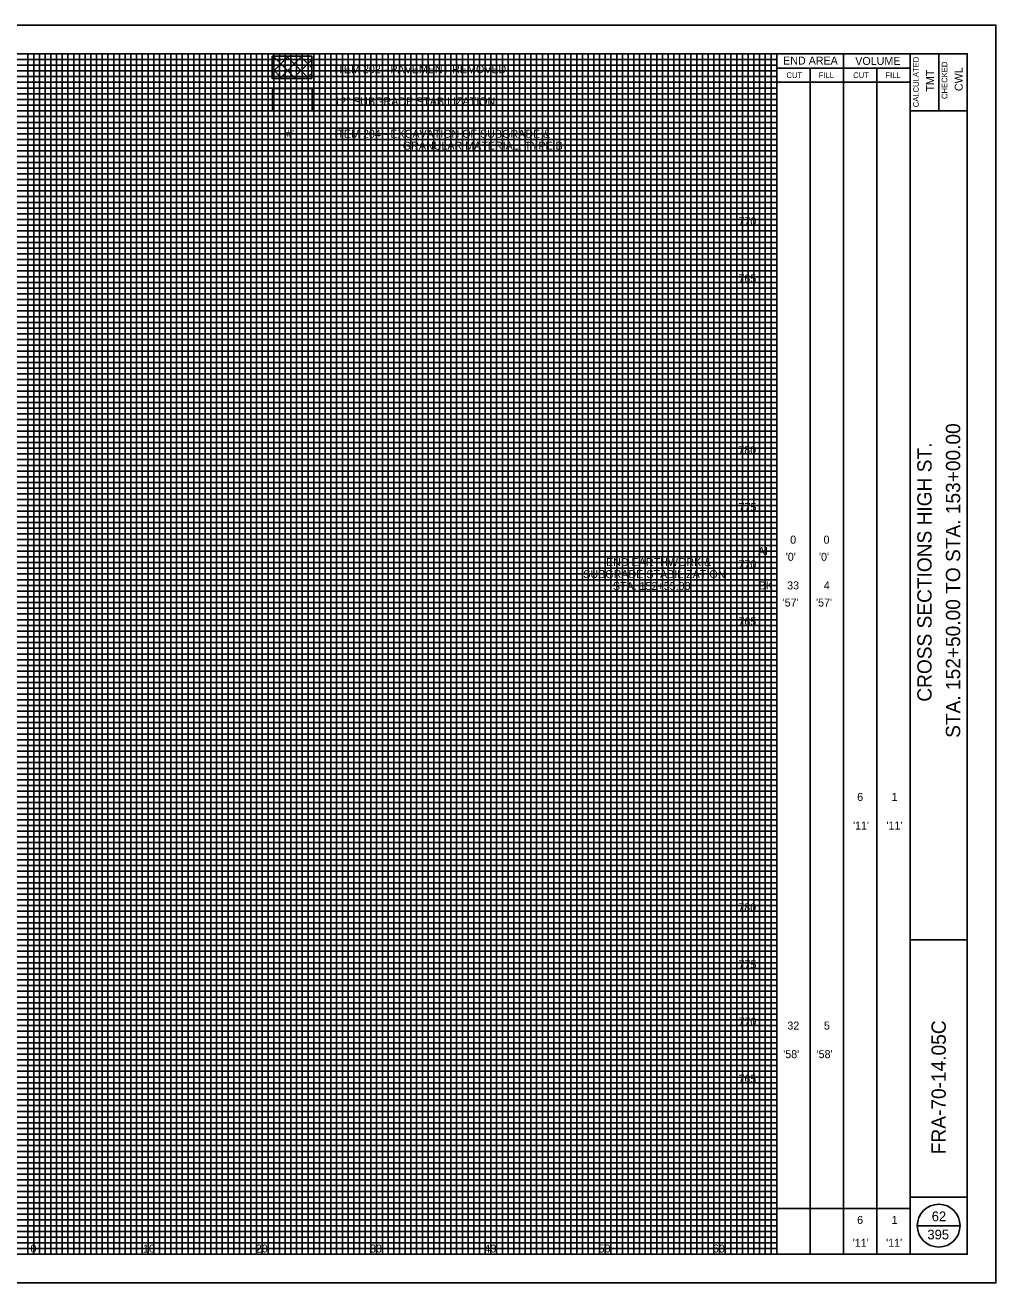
# Model space of a CAD drawing. Extents: x -10 to 160, y -2 to 568.
# Drawn here: x 75.1 to 160, y 457.5 to 567.5 of the extents above; entities that cross this region are included whole.
import ezdxf

# ---------------------------------------------------------------- set-up
doc = ezdxf.new("R2010")
doc.units = 0
for name, color, linetype in [('DR_P_Text', 7, 'Continuous'), ('SV_X_Text_Comment', 7, 'Continuous'), ('SV_X_Text_Elevation', 7, 'Continuous'), ('XS_P_Annotation', 7, 'Continuous'), ('XS_P_Finished_Grade', 7, 'Continuous'), ('XS_P_Pavt_Layers', 7, 'Continuous'), ('XS_P_Shoulder_Surface', 7, 'Continuous'), ('XS_P_Subgrade', 7, 'Continuous'), ('XS_P_Text_MarkedPoint', 7, 'Continuous')]:
    doc.layers.add(name, color=color, linetype=linetype)

msp = doc.modelspace()

# ---------------------------------------------------------------- linework, layer by layer
at = {"layer": 'SV_X_Text_Comment'}
msp.add_lwpolyline([(-10, 457.5), (160, 457.5), (160, 567.5), (-10, 567.5)], close=True, dxfattribs=at)
at = {"layer": 'SV_X_Text_Elevation'}
for p, q in [((5.83, 564.5), (140.83, 564.5)), ((75.33, 460), (75.33, 565)), ((76.33, 460), (76.33, 565)), ((76.83, 460), (76.83, 565)), ((77.33, 460), (77.33, 565)), ((77.83, 460), (77.83, 565)), ((78.33, 460), (78.33, 565)), ((78.83, 460), (78.83, 565)), ((79.33, 460), (79.33, 565)), ((79.83, 460), (79.83, 565)), ((80.33, 460), (80.33, 565)), ((81.33, 460), (81.33, 565)), ((81.83, 460), (81.83, 565)), ((82.33, 460), (82.33, 565)), ((82.83, 460), (82.83, 565)), ((83.33, 460), (83.33, 565)), ((83.83, 460), (83.83, 565)), ((84.33, 460), (84.33, 565)), ((84.83, 460), (84.83, 565)), ((85.33, 460), (85.33, 565)), ((86.33, 460), (86.33, 565)), ((86.83, 460), (86.83, 565)), ((87.33, 460), (87.33, 565)), ((87.83, 460), (87.83, 565)), ((88.33, 460), (88.33, 565)), ((88.83, 460), (88.83, 565)), ((89.33, 460), (89.33, 565)), ((89.83, 460), (89.83, 565)), ((90.33, 460), (90.33, 565)), ((91.33, 460), (91.33, 565)), ((91.83, 460), (91.83, 565)), ((92.33, 460), (92.33, 565)), ((92.83, 460), (92.83, 565)), ((93.33, 460), (93.33, 565)), ((93.83, 460), (93.83, 565)), ((94.33, 460), (94.33, 565)), ((94.83, 460), (94.83, 565)), ((95.33, 460), (95.33, 565)), ((96.33, 460), (96.33, 565)), ((96.83, 460), (96.83, 565)), ((97.33, 460), (97.33, 565)), ((97.83, 460), (97.83, 565)), ((98.33, 460), (98.33, 565)), ((98.83, 460), (98.83, 565)), ((99.33, 460), (99.33, 565)), ((99.83, 460), (99.83, 565)), ((100.33, 460), (100.33, 565)), ((101.33, 460), (101.33, 565)), ((101.83, 460), (101.83, 565)), ((102.33, 460), (102.33, 565)), ((102.83, 460), (102.83, 565)), ((103.33, 460), (103.33, 565)), ((103.83, 460), (103.83, 565)), ((104.33, 460), (104.33, 565)), ((104.83, 460), (104.83, 565)), ((105.33, 460), (105.33, 565)), ((106.33, 460), (106.33, 565)), ((106.83, 460), (106.83, 565)), ((107.33, 460), (107.33, 565)), ((107.83, 460), (107.83, 565)), ((108.33, 460), (108.33, 565)), ((108.83, 460), (108.83, 565)), ((109.33, 460), (109.33, 565)), ((109.83, 460), (109.83, 565)), ((110.33, 460), (110.33, 565)), ((111.33, 460), (111.33, 565)), ((111.83, 460), (111.83, 565)), ((112.33, 460), (112.33, 565)), ((112.83, 460), (112.83, 565)), ((113.33, 460), (113.33, 565)), ((113.83, 460), (113.83, 565)), ((114.33, 460), (114.33, 565)), ((114.83, 460), (114.83, 565)), ((115.33, 460), (115.33, 565)), ((116.33, 460), (116.33, 565)), ((116.83, 460), (116.83, 565)), ((117.33, 460), (117.33, 565)), ((117.83, 460), (117.83, 565)), ((118.33, 460), (118.33, 565)), ((118.83, 460), (118.83, 565)), ((119.33, 460), (119.33, 565)), ((119.83, 460), (119.83, 565)), ((120.33, 460), (120.33, 565)), ((121.33, 460), (121.33, 565)), ((121.83, 460), (121.83, 565)), ((122.33, 460), (122.33, 565)), ((122.83, 460), (122.83, 565)), ((123.33, 460), (123.33, 565)), ((123.83, 460), (123.83, 565)), ((124.33, 460), (124.33, 565)), ((124.83, 460), (124.83, 565)), ((125.33, 460), (125.33, 565)), ((126.33, 460), (126.33, 565)), ((126.83, 460), (126.83, 565)), ((127.33, 460), (127.33, 565)), ((127.83, 460), (127.83, 565)), ((128.33, 460), (128.33, 565)), ((128.83, 460), (128.83, 565)), ((129.33, 460), (129.33, 565)), ((129.83, 460), (129.83, 565)), ((130.33, 460), (130.33, 565)), ((131.33, 460), (131.33, 565)), ((131.83, 460), (131.83, 565)), ((132.33, 460), (132.33, 565)), ((132.83, 460), (132.83, 565)), ((133.33, 460), (133.33, 565)), ((133.83, 460), (133.83, 565)), ((134.33, 460), (134.33, 565)), ((134.83, 460), (134.83, 565)), ((135.33, 460), (135.33, 565)), ((136.33, 460), (136.33, 565)), ((136.83, 460), (136.83, 565)), ((137.33, 460), (137.33, 565)), ((137.83, 460), (137.83, 565)), ((138.33, 460), (138.33, 565)), ((138.83, 460), (138.83, 565)), ((139.33, 460), (139.33, 565)), ((139.83, 460), (139.83, 565)), ((140.33, 460), (140.33, 565)), ((5.83, 564), (140.83, 564)), ((5.83, 563.5), (140.83, 563.5)), ((5.83, 563), (140.83, 563)), ((5.83, 562.5), (140.83, 562.5)), ((5.83, 562), (140.83, 562)), ((5.83, 561.5), (140.83, 561.5)), ((5.83, 561), (140.83, 561)), ((5.83, 560.5), (140.83, 560.5)), ((5.83, 559.5), (140.83, 559.5)), ((5.83, 559), (140.83, 559)), ((5.83, 558.5), (140.83, 558.5)), ((5.83, 558), (140.83, 558)), ((5.83, 557.5), (140.83, 557.5)), ((5.83, 557), (140.83, 557)), ((5.83, 556.5), (140.83, 556.5)), ((5.83, 556), (140.83, 556)), ((5.83, 555.5), (140.83, 555.5)), ((5.83, 554.5), (140.83, 554.5)), ((5.83, 554), (140.83, 554)), ((5.83, 553.5), (140.83, 553.5)), ((5.83, 553), (140.83, 553)), ((5.83, 552.5), (140.83, 552.5)), ((5.83, 552), (140.83, 552)), ((5.83, 551.5), (140.83, 551.5)), ((5.83, 551), (140.83, 551)), ((5.83, 550.5), (140.83, 550.5)), ((5.83, 549.5), (140.83, 549.5)), ((5.83, 549), (140.83, 549)), ((5.83, 548.5), (140.83, 548.5)), ((5.83, 548), (140.83, 548)), ((5.83, 547.5), (140.83, 547.5)), ((5.83, 547), (140.83, 547)), ((5.83, 546.5), (140.83, 546.5)), ((5.83, 546), (140.83, 546)), ((5.83, 545.5), (140.83, 545.5)), ((5.83, 544.5), (140.83, 544.5)), ((5.83, 544), (140.83, 544)), ((5.83, 543.5), (140.83, 543.5)), ((5.83, 543), (140.83, 543)), ((5.83, 542.5), (140.83, 542.5)), ((5.83, 542), (140.83, 542)), ((5.83, 541.5), (140.83, 541.5)), ((5.83, 541), (140.83, 541)), ((5.83, 540.5), (140.83, 540.5)), ((5.83, 539.5), (140.83, 539.5)), ((5.83, 539), (140.83, 539)), ((5.83, 538.5), (140.83, 538.5)), ((5.83, 538), (140.83, 538)), ((5.83, 537.5), (140.83, 537.5)), ((5.83, 537), (140.83, 537)), ((5.83, 536.5), (140.83, 536.5)), ((5.83, 536), (140.83, 536)), ((5.83, 535.5), (140.83, 535.5)), ((5.83, 534.5), (140.83, 534.5)), ((5.83, 534), (140.83, 534)), ((5.83, 533.5), (140.83, 533.5)), ((5.83, 533), (140.83, 533)), ((5.83, 532.5), (140.83, 532.5)), ((5.83, 532), (140.83, 532)), ((5.83, 531.5), (140.83, 531.5)), ((5.83, 531), (140.83, 531)), ((5.83, 530.5), (140.83, 530.5)), ((5.83, 529.5), (140.83, 529.5)), ((5.83, 529), (140.83, 529)), ((5.83, 528.5), (140.83, 528.5)), ((5.83, 528), (140.83, 528)), ((5.83, 527.5), (140.83, 527.5)), ((5.83, 527), (140.83, 527)), ((5.83, 526.5), (140.83, 526.5)), ((5.83, 526), (140.83, 526)), ((5.83, 525.5), (140.83, 525.5)), ((5.83, 524.5), (140.83, 524.5)), ((5.83, 524), (140.83, 524)), ((5.83, 523.5), (140.83, 523.5)), ((5.83, 523), (140.83, 523)), ((5.83, 522.5), (140.83, 522.5)), ((5.83, 522), (140.83, 522)), ((5.83, 521.5), (140.83, 521.5)), ((5.83, 521), (140.83, 521)), ((5.83, 520.5), (140.83, 520.5)), ((5.83, 519.5), (140.83, 519.5)), ((5.83, 519), (140.83, 519)), ((5.83, 518.5), (140.83, 518.5)), ((5.83, 518), (140.83, 518)), ((5.83, 517.5), (140.83, 517.5)), ((5.83, 517), (140.83, 517)), ((5.83, 516.5), (140.83, 516.5)), ((5.83, 516), (140.83, 516)), ((5.83, 515.5), (140.83, 515.5)), ((5.83, 514.5), (140.83, 514.5)), ((5.83, 514), (140.83, 514)), ((5.83, 513.5), (140.83, 513.5)), ((5.83, 513), (140.83, 513)), ((5.83, 512.5), (140.83, 512.5)), ((5.83, 512), (140.83, 512)), ((5.83, 511.5), (140.83, 511.5)), ((5.83, 511), (140.83, 511)), ((5.83, 510.5), (140.83, 510.5)), ((5.83, 509.5), (140.83, 509.5)), ((5.83, 509), (140.83, 509)), ((5.83, 508.5), (140.83, 508.5)), ((5.83, 508), (140.83, 508)), ((5.83, 507.5), (140.83, 507.5)), ((5.83, 507), (140.83, 507)), ((5.83, 506.5), (140.83, 506.5)), ((5.83, 506), (140.83, 506)), ((5.83, 505.5), (140.83, 505.5)), ((5.83, 504.5), (140.83, 504.5)), ((5.83, 504), (140.83, 504)), ((5.83, 503.5), (140.83, 503.5)), ((5.83, 503), (140.83, 503)), ((5.83, 502.5), (140.83, 502.5)), ((5.83, 502), (140.83, 502)), ((5.83, 501.5), (140.83, 501.5)), ((5.83, 501), (140.83, 501)), ((5.83, 500.5), (140.83, 500.5)), ((5.83, 499.5), (140.83, 499.5)), ((5.83, 499), (140.83, 499)), ((5.83, 498.5), (140.83, 498.5)), ((5.83, 498), (140.83, 498)), ((5.83, 497.5), (140.83, 497.5)), ((5.83, 497), (140.83, 497)), ((5.83, 496.5), (140.83, 496.5)), ((5.83, 496), (140.83, 496)), ((5.83, 495.5), (140.83, 495.5)), ((5.83, 494.5), (140.83, 494.5)), ((5.83, 494), (140.83, 494)), ((5.83, 493.5), (140.83, 493.5)), ((5.83, 493), (140.83, 493)), ((5.83, 492.5), (140.83, 492.5)), ((5.83, 492), (140.83, 492)), ((5.83, 491.5), (140.83, 491.5)), ((5.83, 491), (140.83, 491)), ((5.83, 490.5), (140.83, 490.5)), ((5.83, 489.5), (140.83, 489.5)), ((5.83, 489), (140.83, 489)), ((5.83, 488.5), (140.83, 488.5)), ((5.83, 488), (140.83, 488)), ((5.83, 487.5), (140.83, 487.5)), ((5.83, 487), (140.83, 487)), ((5.83, 486.5), (140.83, 486.5)), ((5.83, 486), (140.83, 486)), ((5.83, 485.5), (140.83, 485.5)), ((5.83, 484.5), (140.83, 484.5)), ((5.83, 484), (140.83, 484)), ((5.83, 483.5), (140.83, 483.5)), ((5.83, 483), (140.83, 483)), ((5.83, 482.5), (140.83, 482.5)), ((5.83, 482), (140.83, 482)), ((5.83, 481.5), (140.83, 481.5)), ((5.83, 481), (140.83, 481)), ((5.83, 480.5), (140.83, 480.5)), ((5.83, 479.5), (140.83, 479.5)), ((5.83, 479), (140.83, 479)), ((5.83, 478.5), (140.83, 478.5)), ((5.83, 478), (140.83, 478)), ((5.83, 477.5), (140.83, 477.5)), ((5.83, 477), (140.83, 477)), ((5.83, 476.5), (140.83, 476.5)), ((5.83, 476), (140.83, 476)), ((5.83, 475.5), (140.83, 475.5)), ((5.83, 474.5), (140.83, 474.5)), ((5.83, 474), (140.83, 474)), ((5.83, 473.5), (140.83, 473.5)), ((5.83, 473), (140.83, 473)), ((5.83, 472.5), (140.83, 472.5)), ((5.83, 472), (140.83, 472)), ((5.83, 471.5), (140.83, 471.5)), ((5.83, 471), (140.83, 471)), ((5.83, 470.5), (140.83, 470.5)), ((5.83, 469.5), (140.83, 469.5)), ((5.83, 469), (140.83, 469)), ((5.83, 468.5), (140.83, 468.5)), ((5.83, 468), (140.83, 468)), ((5.83, 467.5), (140.83, 467.5)), ((5.83, 467), (140.83, 467)), ((5.83, 466.5), (140.83, 466.5)), ((5.83, 466), (140.83, 466)), ((5.83, 465.5), (140.83, 465.5)), ((5.83, 464.5), (140.83, 464.5)), ((5.83, 464), (140.83, 464)), ((5.83, 463.5), (140.83, 463.5)), ((5.83, 463), (140.83, 463)), ((5.83, 462.5), (140.83, 462.5)), ((5.83, 462), (140.83, 462)), ((5.83, 461.5), (140.83, 461.5)), ((5.83, 461), (140.83, 461)), ((5.83, 460.5), (140.83, 460.5))]:
    msp.add_line(p, q, dxfattribs=at)
at = {"layer": 'XS_P_Annotation'}
for p, q in [((152.5, 460), (152.5, 565)), ((155, 565), (155, 560)), ((152.5, 560), (157.5, 560)), ((152.5, 487.5), (157.5, 487.5)), ((152.5, 465), (157.5, 465))]:
    msp.add_line(p, q, dxfattribs=at)
msp.add_lwpolyline([(0, 565), (157.5, 565), (157.5, 460), (0, 460)], close=True, dxfattribs=at)
at = {"layer": 'XS_P_Finished_Grade'}
for p, q in [((140.83, 460), (140.83, 565)), ((146.67, 460), (146.67, 565)), ((140.83, 563.75), (152.5, 563.75)), ((143.75, 460), (143.75, 563.75)), ((149.58, 460), (149.58, 563.75)), ((140.83, 562.5), (152.5, 562.5)), ((140.83, 464), (152.5, 464)), ((153.12, 462.5), (156.88, 462.5)), ((142.29, 461), (142.29, 461)), ((145.21, 461), (145.21, 461)), ((148.12, 461), (148.12, 461)), ((151.04, 461), (151.04, 461))]:
    msp.add_line(p, q, dxfattribs=at)
msp.add_circle((155, 462.5), 1.87, dxfattribs=at)
at = {"layer": 'XS_P_Pavt_Layers'}
for p, q in [((96.69, 563.37), (98.11, 564.79)), ((96.78, 564.79), (98.73, 562.84)), ((97.35, 562.84), (99.29, 564.79)), ((97.96, 564.79), (99.91, 562.84)), ((98.52, 562.84), (100.16, 564.48)), ((99.14, 564.79), (100.16, 563.77)), ((96.69, 563.7), (97.55, 562.84)), ((99.7, 562.84), (100.16, 563.3))]:
    msp.add_line(p, q, dxfattribs=at)
at = {"layer": 'XS_P_Shoulder_Surface'}
msp.add_lwpolyline([(96.72, 560.02), (100.19, 560.02), (100.19, 561.96), (96.72, 561.96), (96.72, 560.02)], dxfattribs=at)
at = {"layer": 'XS_P_Subgrade'}
for points in [[(96.69, 564.79), (100.16, 564.79), (100.16, 562.84), (96.69, 562.84)], [(96.72, 561.96), (100.19, 561.96), (100.19, 560.02), (96.72, 560.02)]]:
    msp.add_lwpolyline(points, close=True, dxfattribs=at)
at = {"layer": 'XS_P_Text_MarkedPoint'}
for p, q in [((75.83, 460), (75.83, 565)), ((80.83, 460), (80.83, 565)), ((85.83, 460), (85.83, 565)), ((90.83, 460), (90.83, 565)), ((95.83, 460), (95.83, 565)), ((100.83, 460), (100.83, 565)), ((105.83, 460), (105.83, 565)), ((110.83, 460), (110.83, 565)), ((115.83, 460), (115.83, 565)), ((120.83, 460), (120.83, 565)), ((125.83, 460), (125.83, 565)), ((130.83, 460), (130.83, 565)), ((135.83, 460), (135.83, 565)), ((5.83, 560), (140.83, 560)), ((5.83, 555), (140.83, 555)), ((5.83, 550), (140.83, 550)), ((5.83, 545), (140.83, 545)), ((5.83, 540), (140.83, 540)), ((5.83, 535), (140.83, 535)), ((5.83, 530), (140.83, 530)), ((5.83, 525), (140.83, 525)), ((5.83, 520), (140.83, 520)), ((5.83, 515), (140.83, 515)), ((5.83, 510), (140.83, 510)), ((5.83, 505), (140.83, 505)), ((5.83, 500), (140.83, 500)), ((5.83, 495), (140.83, 495)), ((5.83, 490), (140.83, 490)), ((5.83, 485), (140.83, 485)), ((5.83, 480), (140.83, 480)), ((5.83, 475), (140.83, 475)), ((5.83, 470), (140.83, 470)), ((5.83, 465), (140.83, 465))]:
    msp.add_line(p, q, dxfattribs=at)

# ---------------------------------------------------------------- texts
at = {"layer": 'DR_P_Text'}
for s, p in [("'#'", (97.73, 557.65)), ('770', (137.48, 550)), ('765', (137.48, 545)), ('780', (137.47, 530)), ('775', (137.49, 525)), ('0', (142.01, 522.15)), ('0', (144.93, 522.15)), ('AH', (139.19, 521.15)), ('770', (137.48, 520)), ("'0'", (141.62, 520.65)), ("'0'", (144.53, 520.65)), ('BK', (139.26, 518.15)), ('33', (141.74, 518.15)), ('4', (144.95, 518.15)), ("'57'", (141.35, 516.65)), ("'57'", (144.27, 516.65)), ('765', (137.48, 515)), ('6', (147.87, 499.65)), ('1', (150.88, 499.65)), ("'11'", (147.51, 497.15)), ("'11'", (150.43, 497.15)), ('780', (137.47, 490)), ('775', (137.49, 485)), ('770', (137.48, 480)), ('32', (141.76, 479.65)), ('5', (144.96, 479.65)), ("'58'", (141.4, 477.15)), ("'58'", (144.32, 477.15)), ('765', (137.48, 475)), ('6', (147.87, 462.65)), ('1', (150.88, 462.65)), ("'11'", (147.48, 460.65)), ("'11'", (150.4, 460.65)), ('0', (75.55, 460.15)), ('0', (75.55, 460.15)), ('10', (85.39, 460.15)), ('20', (95.26, 460.15)), ('30', (105.25, 460.15)), ('40', (115.25, 460.15)), ('50', (125.25, 460.15)), ('60', (135.25, 460.15))]:
    msp.add_text(s, height=0.7, dxfattribs=at).set_placement(p)
at = {"layer": 'XS_P_Finished_Grade'}
for s, height, p in [('END AREA', 0.7, (141.39, 564.05)), ('VOLUME', 0.7, (147.7, 564.02)), ('CUT', 0.5, (141.68, 562.87)), ('FILL', 0.5, (144.5, 562.87)), ('CUT', 0.5, (147.52, 562.87)), ('FILL', 0.5, (150.34, 562.87)), ('62', 0.85, (154.39, 462.89)), ('395', 0.85, (154.01, 461.3))]:
    msp.add_text(s, height=height, dxfattribs=at).set_placement(p)
for s, height, p in [('CALCULATED', 0.5, (153.26, 560.32)), ('TMT', 0.7, (154.6, 561.69)), ('CHECKED', 0.5, (155.76, 561.04)), ('CWL', 0.7, (157.1, 561.73)), ('STA. 152+50.00 TO STA. 153+00.00', 1.25, (156.88, 505.17)), ('CROSS SECTIONS HIGH ST.', 1.25, (154.38, 508.33)), ('FRA-70-14.05C', 1.25, (155.62, 468.75))]:
    msp.add_text(s, height=height, rotation=90, dxfattribs=at).set_placement(p)
at = {"layer": 'XS_P_Subgrade'}
for s, p in [('ITEM 202 - PAVEMENT REMOVED', (102.14, 563.3)), ('12" SUBGRADE STABILIZATION', (102.14, 560.48)), ('ITEM 204 - EXCAVATION OF SUBGRADE &', (102.14, 557.65)), ('GRANULAR MATERIAL, TYPE B', (108.12, 556.61)), ('END EARTHWORK &', (125.9, 520.19)), ('SUBGRADE STABILIZATION', (123.91, 519.14)), ('STA. 152+55.00', (126.5, 518.1))]:
    msp.add_text(s, height=0.7, dxfattribs=at).set_placement(p)

doc.saveas('drawing.dxf')
